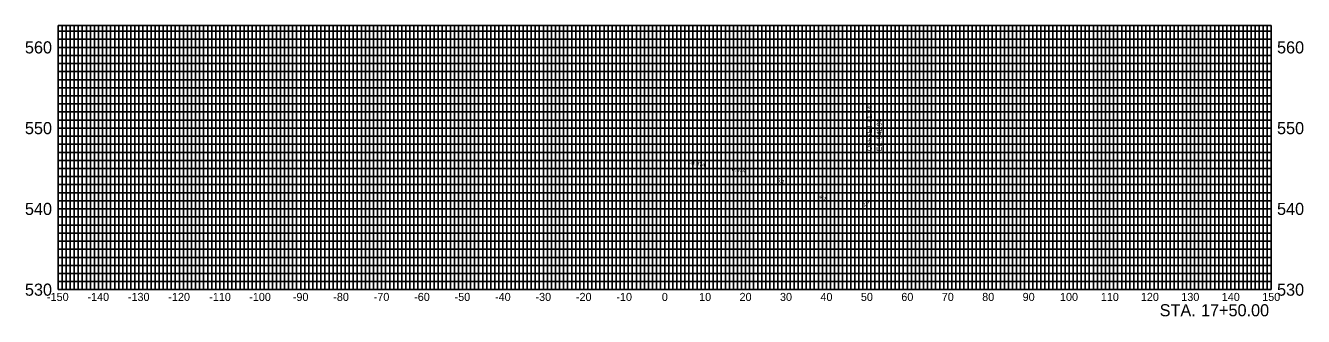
# Model space of a CAD drawing. Extents: x -158 to 158, y 523 to 595.
import ezdxf

# ---------------------------------------------------------------- set-up
doc = ezdxf.new("R2010")
doc.units = 0
for name, color, linetype in [('DES - SHEET - Light Grid', 7, 'Continuous'), ('DES - SHEET - Linework', 7, 'Continuous'), ('DES - XS - Proposed - Finished Grade Slopes Text', 7, 'Continuous'), ('DES - XS - Proposed - Text', 7, 'Continuous')]:
    doc.layers.add(name, color=color, linetype=linetype)

msp = doc.modelspace()

# ---------------------------------------------------------------- linework, layer by layer
at = {"layer": 'DES - SHEET - Light Grid'}
for p, q in [((-149, 530), (-149, 595.41)), ((-148, 530), (-148, 595.41)), ((-147, 530), (-147, 595.41)), ((-146, 530), (-146, 595.41)), ((-145, 530), (-145, 595.41)), ((-144, 530), (-144, 595.41)), ((-143, 530), (-143, 595.41)), ((-142, 530), (-142, 595.41)), ((-141, 530), (-141, 595.41)), ((-139, 530), (-139, 595.41)), ((-138, 530), (-138, 595.41)), ((-137, 530), (-137, 595.41)), ((-136, 530), (-136, 595.41)), ((-135, 530), (-135, 595.41)), ((-134, 530), (-134, 595.41)), ((-133, 530), (-133, 595.41)), ((-132, 530), (-132, 595.41)), ((-131, 530), (-131, 595.41)), ((-129, 530), (-129, 595.41)), ((-128, 530), (-128, 595.41)), ((-127, 530), (-127, 595.41)), ((-126, 530), (-126, 595.41)), ((-125, 530), (-125, 595.41)), ((-124, 530), (-124, 595.41)), ((-123, 530), (-123, 595.41)), ((-122, 530), (-122, 595.41)), ((-121, 530), (-121, 595.41)), ((-119, 530), (-119, 595.41)), ((-118, 530), (-118, 595.41)), ((-117, 530), (-117, 595.41)), ((-116, 530), (-116, 595.41)), ((-115, 530), (-115, 595.41)), ((-114, 530), (-114, 595.41)), ((-113, 530), (-113, 595.41)), ((-112, 530), (-112, 595.41)), ((-111, 530), (-111, 595.41)), ((-109, 530), (-109, 595.41)), ((-108, 530), (-108, 595.41)), ((-107, 530), (-107, 595.41)), ((-106, 530), (-106, 595.41)), ((-105, 530), (-105, 595.41)), ((-104, 530), (-104, 595.41)), ((-103, 530), (-103, 595.41)), ((-102, 530), (-102, 595.41)), ((-101, 530), (-101, 595.41)), ((-99, 530), (-99, 595.41)), ((-98, 530), (-98, 595.41)), ((-97, 530), (-97, 595.41)), ((-96, 530), (-96, 595.41)), ((-95, 530), (-95, 595.41)), ((-94, 530), (-94, 595.41)), ((-93, 530), (-93, 595.41)), ((-92, 530), (-92, 595.41)), ((-91, 530), (-91, 595.41)), ((-89, 530), (-89, 595.41)), ((-88, 530), (-88, 595.41)), ((-87, 530), (-87, 595.41)), ((-86, 530), (-86, 595.41)), ((-85, 530), (-85, 595.41)), ((-84, 530), (-84, 595.41)), ((-83, 530), (-83, 595.41)), ((-82, 530), (-82, 595.41)), ((-81, 530), (-81, 595.41)), ((-79, 530), (-79, 595.41)), ((-78, 530), (-78, 595.41)), ((-77, 530), (-77, 595.41)), ((-76, 530), (-76, 595.41)), ((-75, 530), (-75, 595.41)), ((-74, 530), (-74, 595.41)), ((-73, 530), (-73, 595.41)), ((-72, 530), (-72, 595.41)), ((-71, 530), (-71, 595.41)), ((-69, 530), (-69, 595.41)), ((-68, 530), (-68, 595.41)), ((-67, 530), (-67, 595.41)), ((-66, 530), (-66, 595.41)), ((-65, 530), (-65, 595.41)), ((-64, 530), (-64, 595.41)), ((-63, 530), (-63, 595.41)), ((-62, 530), (-62, 595.41)), ((-61, 530), (-61, 595.41)), ((-59, 530), (-59, 595.41)), ((-58, 530), (-58, 595.41)), ((-57, 530), (-57, 595.41)), ((-56, 530), (-56, 595.41)), ((-55, 530), (-55, 595.41)), ((-54, 530), (-54, 595.41)), ((-53, 530), (-53, 595.41)), ((-52, 530), (-52, 595.41)), ((-51, 530), (-51, 595.41)), ((-49, 530), (-49, 595.41)), ((-48, 530), (-48, 595.41)), ((-47, 530), (-47, 595.41)), ((-46, 530), (-46, 595.41)), ((-45, 530), (-45, 595.41)), ((-44, 530), (-44, 595.41)), ((-43, 530), (-43, 595.41)), ((-42, 530), (-42, 595.41)), ((-41, 530), (-41, 595.41)), ((-39, 530), (-39, 595.41)), ((-38, 530), (-38, 595.41)), ((-37, 530), (-37, 595.41)), ((-36, 530), (-36, 595.41)), ((-35, 530), (-35, 595.41)), ((-34, 530), (-34, 595.41)), ((-33, 530), (-33, 595.41)), ((-32, 530), (-32, 595.41)), ((-31, 530), (-31, 595.41)), ((-29, 530), (-29, 595.41)), ((-28, 530), (-28, 595.41)), ((-27, 530), (-27, 595.41)), ((-26, 530), (-26, 595.41)), ((-25, 530), (-25, 595.41)), ((-24, 530), (-24, 595.41)), ((-23, 530), (-23, 595.41)), ((-22, 530), (-22, 595.41)), ((-21, 530), (-21, 595.41)), ((-19, 530), (-19, 595.41)), ((-18, 530), (-18, 595.41)), ((-17, 530), (-17, 595.41)), ((-16, 530), (-16, 595.41)), ((-15, 530), (-15, 595.41)), ((-14, 530), (-14, 595.41)), ((-13, 530), (-13, 595.41)), ((-12, 530), (-12, 595.41)), ((-11, 530), (-11, 595.41)), ((-9, 530), (-9, 595.41)), ((-8, 530), (-8, 595.41)), ((-7, 530), (-7, 595.41)), ((-6, 530), (-6, 595.41)), ((-5, 530), (-5, 595.41)), ((-4, 530), (-4, 595.41)), ((-3, 530), (-3, 595.41)), ((-2, 530), (-2, 595.41)), ((-1, 530), (-1, 595.41)), ((1, 530), (1, 595.41)), ((2, 530), (2, 595.41)), ((3, 530), (3, 595.41)), ((4, 530), (4, 595.41)), ((5, 530), (5, 595.41)), ((6, 530), (6, 595.41)), ((7, 530), (7, 595.41)), ((8, 530), (8, 595.41)), ((9, 530), (9, 595.41)), ((11, 530), (11, 595.41)), ((12, 530), (12, 595.41)), ((13, 530), (13, 595.41)), ((14, 530), (14, 595.41)), ((15, 530), (15, 595.41)), ((16, 530), (16, 595.41)), ((17, 530), (17, 595.41)), ((18, 530), (18, 595.41)), ((19, 530), (19, 595.41)), ((21, 530), (21, 595.41)), ((22, 530), (22, 595.41)), ((23, 530), (23, 595.41)), ((24, 530), (24, 595.41)), ((25, 530), (25, 595.41)), ((26, 530), (26, 595.41)), ((27, 530), (27, 595.41)), ((28, 530), (28, 595.41)), ((29, 530), (29, 595.41)), ((31, 530), (31, 595.41)), ((32, 530), (32, 595.41)), ((33, 530), (33, 595.41)), ((34, 530), (34, 595.41)), ((35, 530), (35, 595.41)), ((36, 530), (36, 595.41)), ((37, 530), (37, 595.41)), ((38, 530), (38, 595.41)), ((39, 530), (39, 595.41)), ((41, 530), (41, 595.41)), ((42, 530), (42, 595.41)), ((43, 530), (43, 595.41)), ((44, 530), (44, 595.41)), ((45, 530), (45, 595.41)), ((46, 530), (46, 595.41)), ((47, 530), (47, 595.41)), ((48, 530), (48, 595.41)), ((49, 530), (49, 595.41)), ((51, 530), (51, 595.41)), ((52, 530), (52, 595.41)), ((53, 530), (53, 595.41)), ((54, 530), (54, 595.41)), ((55, 530), (55, 595.41)), ((56, 530), (56, 595.41)), ((57, 530), (57, 595.41)), ((58, 530), (58, 595.41)), ((59, 530), (59, 595.41)), ((61, 530), (61, 595.41)), ((62, 530), (62, 595.41)), ((63, 530), (63, 595.41)), ((64, 530), (64, 595.41)), ((65, 530), (65, 595.41)), ((66, 530), (66, 595.41)), ((67, 530), (67, 595.41)), ((68, 530), (68, 595.41)), ((69, 530), (69, 595.41)), ((71, 530), (71, 595.41)), ((72, 530), (72, 595.41)), ((73, 530), (73, 595.41)), ((74, 530), (74, 595.41)), ((75, 530), (75, 595.41)), ((76, 530), (76, 595.41)), ((77, 530), (77, 595.41)), ((78, 530), (78, 595.41)), ((79, 530), (79, 595.41)), ((81, 530), (81, 595.41)), ((82, 530), (82, 595.41)), ((83, 530), (83, 595.41)), ((84, 530), (84, 595.41)), ((85, 530), (85, 595.41)), ((86, 530), (86, 595.41)), ((87, 530), (87, 595.41)), ((88, 530), (88, 595.41)), ((89, 530), (89, 595.41)), ((91, 530), (91, 595.41)), ((92, 530), (92, 595.41)), ((93, 530), (93, 595.41)), ((94, 530), (94, 595.41)), ((95, 530), (95, 595.41)), ((96, 530), (96, 595.41)), ((97, 530), (97, 595.41)), ((98, 530), (98, 595.41)), ((99, 530), (99, 595.41)), ((101, 530), (101, 595.41)), ((102, 530), (102, 595.41)), ((103, 530), (103, 595.41)), ((104, 530), (104, 595.41)), ((105, 530), (105, 595.41)), ((106, 530), (106, 595.41)), ((107, 530), (107, 595.41)), ((108, 530), (108, 595.41)), ((109, 530), (109, 595.41)), ((111, 530), (111, 595.41)), ((112, 530), (112, 595.41)), ((113, 530), (113, 595.41)), ((114, 530), (114, 595.41)), ((115, 530), (115, 595.41)), ((116, 530), (116, 595.41)), ((117, 530), (117, 595.41)), ((118, 530), (118, 595.41)), ((119, 530), (119, 595.41)), ((121, 530), (121, 595.41)), ((122, 530), (122, 595.41)), ((123, 530), (123, 595.41)), ((124, 530), (124, 595.41)), ((125, 530), (125, 595.41)), ((126, 530), (126, 595.41)), ((127, 530), (127, 595.41)), ((128, 530), (128, 595.41)), ((129, 530), (129, 595.41)), ((131, 530), (131, 595.41)), ((132, 530), (132, 595.41)), ((133, 530), (133, 595.41)), ((134, 530), (134, 595.41)), ((135, 530), (135, 595.41)), ((136, 530), (136, 595.41)), ((137, 530), (137, 595.41)), ((138, 530), (138, 595.41)), ((139, 530), (139, 595.41)), ((141, 530), (141, 595.41)), ((142, 530), (142, 595.41)), ((143, 530), (143, 595.41)), ((144, 530), (144, 595.41)), ((145, 530), (145, 595.41)), ((146, 530), (146, 595.41)), ((147, 530), (147, 595.41)), ((148, 530), (148, 595.41)), ((149, 530), (149, 595.41)), ((-150, 594), (150, 594)), ((-150, 592), (150, 592)), ((-150, 588), (150, 588)), ((-150, 586), (150, 586)), ((-150, 584), (150, 584)), ((-150, 582), (150, 582)), ((-150, 580), (150, 580)), ((-150, 578), (150, 578)), ((-150, 576), (150, 576)), ((-150, 574), (150, 574)), ((-150, 572), (150, 572)), ((-150, 568), (150, 568)), ((-150, 566), (150, 566)), ((-150, 564), (150, 564)), ((-150, 562), (150, 562)), ((-150, 560), (150, 560)), ((-150, 558), (150, 558)), ((-150, 556), (150, 556)), ((-150, 554), (150, 554)), ((-150, 552), (150, 552)), ((-150, 548), (150, 548)), ((-150, 546), (150, 546)), ((-150, 544), (150, 544)), ((-150, 542), (150, 542)), ((-150, 540), (150, 540)), ((-150, 538), (150, 538)), ((-150, 536), (150, 536)), ((-150, 534), (150, 534)), ((-150, 532), (150, 532))]:
    msp.add_line(p, q, dxfattribs=at)
at = {"layer": 'DES - SHEET - Linework'}
for p, q in [((-150, 595.41), (150, 595.41)), ((-150, 530), (-150, 595.41)), ((-140, 530), (-140, 595.41)), ((-130, 530), (-130, 595.41)), ((-120, 530), (-120, 595.41)), ((-110, 530), (-110, 595.41)), ((-100, 530), (-100, 595.41)), ((-90, 530), (-90, 595.41)), ((-80, 530), (-80, 595.41)), ((-70, 530), (-70, 595.41)), ((-60, 530), (-60, 595.41)), ((-50, 530), (-50, 595.41)), ((-40, 530), (-40, 595.41)), ((-30, 530), (-30, 595.41)), ((-20, 530), (-20, 595.41)), ((-10, 530), (-10, 595.41)), ((0, 530), (0, 595.41)), ((10, 530), (10, 595.41)), ((20, 530), (20, 595.41)), ((30, 530), (30, 595.41)), ((40, 530), (40, 595.41)), ((50, 530), (50, 595.41)), ((60, 530), (60, 595.41)), ((70, 530), (70, 595.41)), ((80, 530), (80, 595.41)), ((90, 530), (90, 595.41)), ((100, 530), (100, 595.41)), ((110, 530), (110, 595.41)), ((120, 530), (120, 595.41)), ((130, 530), (130, 595.41)), ((140, 530), (140, 595.41)), ((150, 530), (150, 595.41)), ((-150, 590), (150, 590)), ((-150, 570), (150, 570)), ((-150, 550), (150, 550)), ((-150, 530), (150, 530))]:
    msp.add_line(p, q, dxfattribs=at)

# ---------------------------------------------------------------- texts
at = {"layer": 'DES - XS - Proposed - Finished Grade Slopes Text'}
for s, height, rotation, p in [("51.84'", 1.2, 90, (51.24, 571.37)), ('542.96', 1.2, 90, (53.64, 567.3)), ('OFFSET ', 1.2, 90, (51.24, 564.32)), ('EL. ', 1.2, 90, (53.64, 564.32)), ('-0.074', 1, 351.5948, (6.08, 560.97)), ('-0.074', 1, 351.5948, (16.08, 559.49)), ('6:1', 1, 341.5651, (27.67, 556.72)), ('4:1', 1, 333.4349, (38.04, 552.75)), ('2:1', 1, 46.8396, (49.41, 550.45))]:
    msp.add_text(s, height=height, rotation=rotation, dxfattribs=at).set_placement(p)
at = {"layer": 'DES - XS - Proposed - Text'}
for s, height, p in [('560', 3, (-158.19, 588.5)), ('560', 3, (151.41, 588.5)), ('550', 3, (-158.19, 568.5)), ('550', 3, (151.41, 568.5)), ('540', 3, (-158.19, 548.5)), ('540', 3, (151.41, 548.5)), ('530', 3, (-158.19, 528.5)), ('530', 3, (151.41, 528.5)), ('-150', 2, (-152.73, 527.2)), ('-140', 2, (-142.73, 527.2)), ('-130', 2, (-132.73, 527.2)), ('-120', 2, (-122.73, 527.2)), ('-110', 2, (-112.62, 527.2)), ('-100', 2, (-102.73, 527.2)), ('-90', 2, (-91.95, 527.2)), ('-80', 2, (-81.95, 527.2)), ('-70', 2, (-71.95, 527.2)), ('-60', 2, (-61.95, 527.2)), ('-50', 2, (-51.95, 527.2)), ('-40', 2, (-41.95, 527.2)), ('-30', 2, (-31.95, 527.2)), ('-20', 2, (-21.95, 527.2)), ('-10', 2, (-11.95, 527.2)), ('0', 2, (-0.71, 527.2)), ('10', 2, (8.51, 527.2)), ('20', 2, (18.51, 527.2)), ('30', 2, (28.51, 527.2)), ('40', 2, (38.51, 527.2)), ('50', 2, (48.51, 527.2)), ('60', 2, (58.51, 527.2)), ('70', 2, (68.51, 527.2)), ('80', 2, (78.51, 527.2)), ('90', 2, (88.51, 527.2)), ('100', 2, (97.74, 527.2)), ('110', 2, (107.84, 527.2)), ('120', 2, (117.74, 527.2)), ('130', 2, (127.74, 527.2)), ('140', 2, (137.74, 527.2)), ('150', 2, (147.74, 527.2)), (' STA. ', 3, (121.28, 523.4)), ('17+50.00', 3, (132.61, 523.4))]:
    msp.add_text(s, height=height, dxfattribs=at).set_placement(p)

doc.saveas('drawing.dxf')
